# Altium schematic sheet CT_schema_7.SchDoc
size 253 x 245 mm
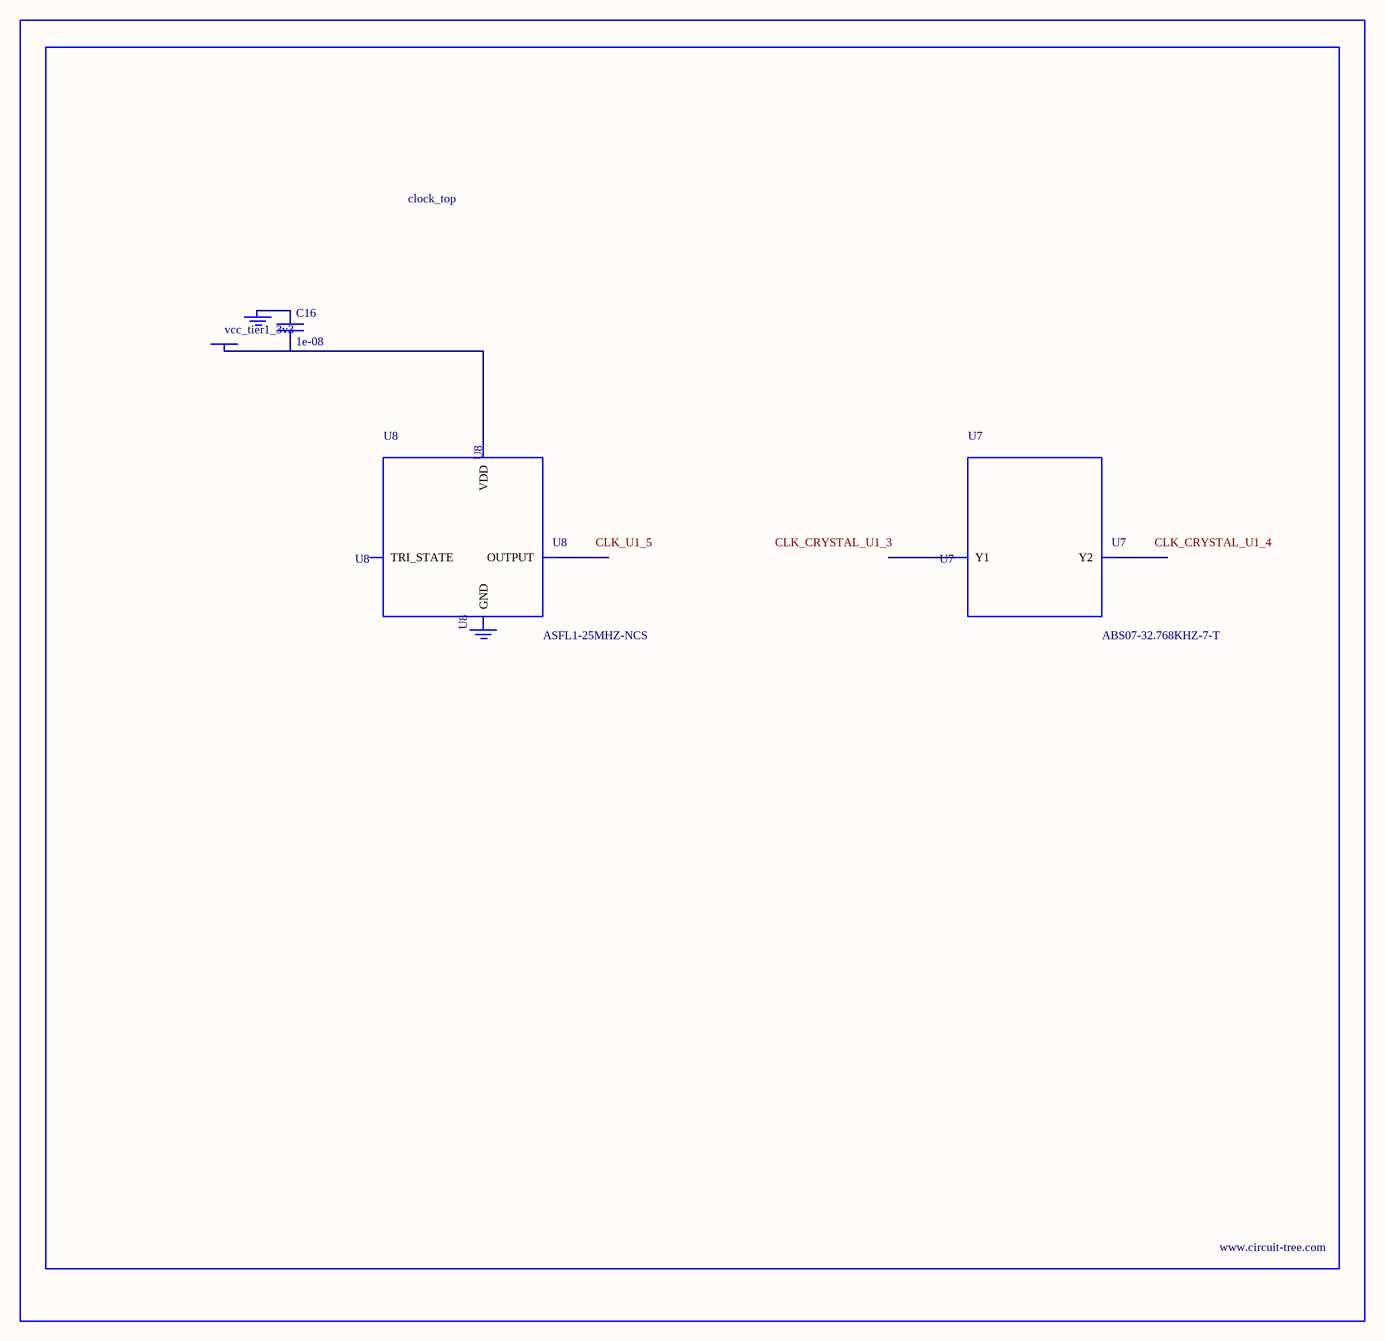
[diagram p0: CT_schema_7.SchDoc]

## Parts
BORDER6  (no value)
C16  1e-08  [C0402]
GND_INSTANCE_6_0  (no value)
GND_INSTANCE_6_1  (no value)
POWER_INSTANCE_6_0  vcc_tier1_3v3
U7  ABS07-32.768KHZ-7-T  [ABS07-32.768KHZ-7-T]
U8  ASFL1-25MHZ-NCS  [ASFL1]

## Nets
NetC16_1: C16.1 GND_INSTANCE_6_0.0(GND)
NetC16_2: C16.2 POWER_INSTANCE_6_0.0(PWR) U8.4(VDD)

Not connected (* = marked no-connect by the designer): GND_INSTANCE_6_1 0(GND); U7 1(Y1) 2(Y2); U8 1(TRI_STATE) 2(GND) 3(OUTPUT)

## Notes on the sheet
- Labels drawn without touching a wire or pin: CLK_CRYSTAL_U1_3, CLK_CRYSTAL_U1_4, CLK_U1_5

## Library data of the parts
BORDER6 = BORDER_PAGE6
C16 = C0402C103K3RAC
GND_INSTANCE_6_0 GND_INSTANCE_6_1 = GND
POWER_INSTANCE_6_0 = PWR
